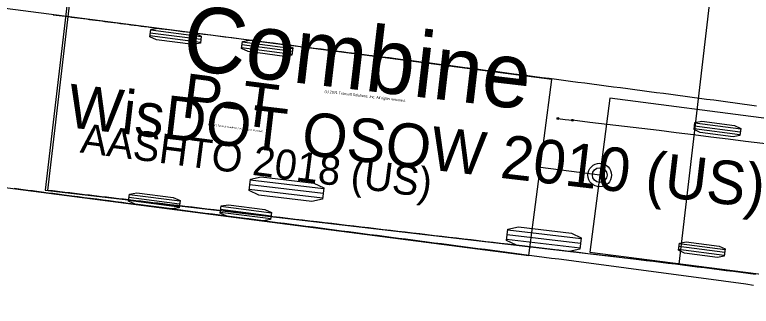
# Model space of a CAD drawing. Extents: x -14 to 1565148, y -25 to 642856.
# Drawn here: x 1564698.39 to 1564731.62, y 636284.95 to 636298.09 of the extents above; entities that cross this region are included whole.
import ezdxf

# ---------------------------------------------------------------- set-up
doc = ezdxf.new("R2010")
doc.units = 0
doc.layers.add('PV_P_Curb', color=7, linetype='Continuous')

msp = doc.modelspace()

# ---------------------------------------------------------------- linework, layer by layer
at = {"layer": 'PV_P_Curb'}
for p, q in [((1564701.133, 636301.885), (1564699.765, 636290.185)), ((1564722.618, 636295.178), (1564695.843, 636298.65)), ((1564728.37, 636286.841), (1564729.738, 636298.541)), ((1564706.801, 636297.098), (1564704.52, 636297.394)), ((1564706.767, 636296.84), (1564704.486, 636297.136)), ((1564706.784, 636296.969), (1564704.503, 636297.265)), ((1564710.916, 636296.433), (1564708.635, 636296.729)), ((1564710.933, 636296.562), (1564708.652, 636296.858)), ((1564710.899, 636296.304), (1564708.618, 636296.6)), ((1564721.59, 636287.245), (1564722.618, 636295.178)), ((1564722.618, 636295.178), (1564722.618, 636295.178)), ((1564725.232, 636294.335), (1564724.332, 636287.393)), ((1564744.074, 636291.892), (1564725.232, 636294.335)), ((1564731.125, 636292.804), (1564729.059, 636293.072)), ((1564731.142, 636292.933), (1564729.076, 636293.201)), ((1564731.109, 636292.675), (1564729.043, 636292.943)), ((1564724.782, 636290.864), (1564722.104, 636291.211)), ((1564694.814, 636290.717), (1564721.59, 636287.245)), ((1564724.782, 636290.864), (1564724.782, 636290.864)), ((1564712.299, 636290.035), (1564708.988, 636290.422)), ((1564712.323, 636290.242), (1564709.013, 636290.629)), ((1564699.765, 636290.185), (1564728.37, 636286.841)), ((1564712.275, 636289.828), (1564708.964, 636290.215)), ((1564705.805, 636289.423), (1564703.524, 636289.718)), ((1564705.822, 636289.552), (1564703.541, 636289.848)), ((1564705.839, 636289.681), (1564703.558, 636289.977)), ((1564709.971, 636289.145), (1564707.69, 636289.441)), ((1564709.937, 636288.887), (1564707.657, 636289.183)), ((1564709.954, 636289.016), (1564707.673, 636289.312)), ((1564723.916, 636287.781), (1564720.605, 636288.168)), ((1564723.94, 636287.988), (1564720.629, 636288.375)), ((1564723.892, 636287.574), (1564720.581, 636287.961)), ((1564730.438, 636287.5), (1564728.372, 636287.768)), ((1564724.332, 636287.393), (1564743.174, 636284.95)), ((1564730.404, 636287.241), (1564728.338, 636287.509)), ((1564730.421, 636287.371), (1564728.355, 636287.638))]:
    msp.add_line(p, q, dxfattribs=at)
for points in [[(1564731.805, 636286.385), (1564731.477, 636286.427), (1564731.149, 636286.469), (1564730.821, 636286.511), (1564730.492, 636286.553), (1564730.164, 636286.594), (1564729.836, 636286.636), (1564729.508, 636286.677), (1564729.179, 636286.718), (1564728.851, 636286.759), (1564728.523, 636286.8), (1564728.194, 636286.841), (1564727.866, 636286.882), (1564727.537, 636286.922), (1564727.209, 636286.963), (1564726.88, 636287.003), (1564726.552, 636287.043), (1564726.223, 636287.083), (1564725.895, 636287.123), (1564725.566, 636287.163), (1564725.238, 636287.202), (1564724.909, 636287.242), (1564724.581, 636287.281), (1564724.252, 636287.32), (1564723.923, 636287.359), (1564723.594, 636287.398), (1564723.265, 636287.437), (1564722.936, 636287.476), (1564722.607, 636287.514), (1564722.278, 636287.553), (1564721.948, 636287.591), (1564721.619, 636287.63), (1564721.289, 636287.668), (1564720.96, 636287.707), (1564720.63, 636287.745), (1564720.3, 636287.784), (1564719.97, 636287.823), (1564719.64, 636287.861), (1564719.31, 636287.9), (1564718.98, 636287.938), (1564718.65, 636287.977), (1564718.319, 636288.016), (1564717.989, 636288.054), (1564717.658, 636288.093), (1564717.327, 636288.132), (1564716.997, 636288.17), (1564716.666, 636288.209), (1564716.335, 636288.248), (1564716.004, 636288.286), (1564715.673, 636288.325), (1564715.342, 636288.364), (1564715.011, 636288.402), (1564714.679, 636288.441), (1564714.348, 636288.48), (1564714.017, 636288.519), (1564713.685, 636288.557), (1564713.354, 636288.596), (1564713.022, 636288.635), (1564712.691, 636288.674), (1564712.359, 636288.712), (1564712.028, 636288.751), (1564711.696, 636288.79), (1564711.364, 636288.829), (1564711.032, 636288.867), (1564710.701, 636288.906), (1564710.369, 636288.945), (1564710.037, 636288.984), (1564709.705, 636289.023), (1564709.373, 636289.061), (1564709.042, 636289.1), (1564708.71, 636289.139), (1564708.378, 636289.178), (1564708.047, 636289.216), (1564707.715, 636289.255), (1564707.383, 636289.294), (1564707.052, 636289.333), (1564706.72, 636289.372), (1564706.389, 636289.41), (1564706.058, 636289.449), (1564705.726, 636289.488), (1564705.395, 636289.526), (1564705.284, 636289.539), (1564705.174, 636289.552), (1564705.063, 636289.565), (1564704.953, 636289.578), (1564704.842, 636289.591), (1564704.732, 636289.604), (1564704.621, 636289.617), (1564704.511, 636289.63), (1564704.4, 636289.643), (1564704.29, 636289.656), (1564704.18, 636289.669), (1564704.069, 636289.681), (1564703.959, 636289.694), (1564703.848, 636289.707), (1564703.738, 636289.72), (1564703.628, 636289.733), (1564703.517, 636289.746), (1564703.407, 636289.759), (1564703.297, 636289.772), (1564703.186, 636289.785), (1564703.076, 636289.798), (1564702.966, 636289.81), (1564702.855, 636289.823), (1564702.745, 636289.836), (1564702.635, 636289.849), (1564702.524, 636289.862), (1564702.414, 636289.875), (1564702.303, 636289.888), (1564702.193, 636289.901), (1564702.083, 636289.914), (1564701.972, 636289.927), (1564701.862, 636289.939), (1564701.752, 636289.952), (1564701.641, 636289.965), (1564701.531, 636289.978), (1564701.421, 636289.991), (1564701.31, 636290.004), (1564701.2, 636290.017), (1564701.089, 636290.03), (1564700.979, 636290.043), (1564700.869, 636290.056), (1564700.758, 636290.069), (1564700.648, 636290.081), (1564700.538, 636290.094), (1564700.427, 636290.107), (1564700.317, 636290.12), (1564700.207, 636290.133), (1564700.096, 636290.146), (1564699.986, 636290.159), (1564699.876, 636290.172), (1564701.243, 636301.873)], [(1564700.123, 636298.095), (1564700.259, 636298.078), (1564700.396, 636298.06), (1564700.532, 636298.042), (1564700.668, 636298.024), (1564700.805, 636298.007), (1564700.941, 636297.989), (1564701.078, 636297.971), (1564701.215, 636297.954), (1564701.351, 636297.936), (1564701.488, 636297.918), (1564701.625, 636297.9), (1564701.762, 636297.883), (1564701.9, 636297.865), (1564702.037, 636297.847), (1564702.174, 636297.829), (1564702.312, 636297.811), (1564702.449, 636297.794), (1564702.587, 636297.776), (1564702.724, 636297.758), (1564702.862, 636297.74), (1564703, 636297.722), (1564703.153, 636297.702), (1564703.31, 636297.682), (1564703.467, 636297.662), (1564703.624, 636297.641), (1564703.78, 636297.621), (1564703.935, 636297.601), (1564704.091, 636297.581), (1564704.245, 636297.561), (1564704.4, 636297.542), (1564704.554, 636297.522), (1564704.708, 636297.502), (1564705.014, 636297.463), (1564705.335, 636297.422), (1564705.654, 636297.381), (1564705.973, 636297.341), (1564706.291, 636297.3), (1564706.609, 636297.26), (1564706.925, 636297.22), (1564707.241, 636297.179), (1564707.556, 636297.139), (1564707.87, 636297.099), (1564708.184, 636297.06), (1564708.496, 636297.02), (1564708.808, 636296.98), (1564709.12, 636296.941), (1564709.431, 636296.901), (1564709.741, 636296.862), (1564710.051, 636296.822), (1564710.36, 636296.783), (1564710.669, 636296.744), (1564710.977, 636296.704), (1564711.286, 636296.665), (1564711.593, 636296.626), (1564711.901, 636296.587), (1564712.208, 636296.548), (1564712.515, 636296.509), (1564712.822, 636296.47), (1564713.129, 636296.431), (1564713.436, 636296.392), (1564713.743, 636296.352), (1564714.049, 636296.313), (1564714.356, 636296.274), (1564714.663, 636296.235), (1564714.97, 636296.196), (1564715.278, 636296.157), (1564715.586, 636296.117), (1564715.894, 636296.078), (1564716.202, 636296.038), (1564716.511, 636295.999), (1564716.821, 636295.959), (1564717.131, 636295.919), (1564717.441, 636295.88), (1564717.753, 636295.84), (1564718.065, 636295.8), (1564718.377, 636295.759), (1564718.691, 636295.719), (1564719.005, 636295.679), (1564719.319, 636295.638), (1564719.635, 636295.597), (1564719.951, 636295.557), (1564720.268, 636295.516), (1564720.585, 636295.475), (1564720.904, 636295.434), (1564721.222, 636295.392), (1564721.542, 636295.351), (1564721.861, 636295.309), (1564722.182, 636295.268), (1564722.502, 636295.226), (1564722.824, 636295.184), (1564723.145, 636295.143), (1564723.467, 636295.101), (1564723.789, 636295.059), (1564724.111, 636295.017), (1564724.433, 636294.974), (1564724.756, 636294.932), (1564725.079, 636294.89), (1564725.402, 636294.847), (1564725.725, 636294.805), (1564726.047, 636294.763), (1564726.37, 636294.72), (1564726.694, 636294.677), (1564727.017, 636294.635), (1564727.34, 636294.592), (1564727.663, 636294.549), (1564727.986, 636294.507), (1564728.309, 636294.464), (1564728.632, 636294.421), (1564728.955, 636294.378), (1564729.278, 636294.335), (1564729.601, 636294.292), (1564729.924, 636294.249), (1564730.247, 636294.206), (1564730.57, 636294.162), (1564730.893, 636294.119), (1564731.216, 636294.076), (1564731.539, 636294.032), (1564731.863, 636293.989)], [(1564722.896, 636293.411), (1564723.227, 636293.372), (1564723.558, 636293.333)], [(1564731.718, 636285.893), (1564731.38, 636285.939), (1564731.043, 636285.985), (1564730.705, 636286.03), (1564730.367, 636286.076), (1564730.029, 636286.122), (1564729.691, 636286.167), (1564729.354, 636286.213), (1564729.016, 636286.258), (1564728.678, 636286.303), (1564728.34, 636286.349), (1564728.002, 636286.394), (1564727.664, 636286.439), (1564727.327, 636286.484), (1564726.989, 636286.529), (1564726.651, 636286.574), (1564726.313, 636286.619), (1564725.976, 636286.664), (1564725.638, 636286.709), (1564725.301, 636286.754), (1564724.963, 636286.799), (1564724.626, 636286.843), (1564724.289, 636286.888), (1564723.952, 636286.932), (1564723.615, 636286.977), (1564723.279, 636287.021), (1564722.943, 636287.066), (1564722.607, 636287.11), (1564722.271, 636287.154), (1564721.937, 636287.198), (1564721.602, 636287.242), (1564721.268, 636287.285), (1564720.935, 636287.329), (1564720.603, 636287.373), (1564720.271, 636287.416), (1564719.939, 636287.459), (1564719.609, 636287.502), (1564719.279, 636287.544), (1564718.95, 636287.587), (1564718.622, 636287.63), (1564718.294, 636287.672), (1564717.967, 636287.714), (1564717.641, 636287.757), (1564717.316, 636287.799), (1564716.991, 636287.841), (1564716.667, 636287.883), (1564716.343, 636287.925), (1564716.02, 636287.967), (1564715.698, 636288.009), (1564715.375, 636288.05), (1564715.054, 636288.092), (1564714.732, 636288.134), (1564714.411, 636288.175), (1564714.09, 636288.217), (1564713.77, 636288.259), (1564713.449, 636288.3), (1564713.128, 636288.342), (1564712.808, 636288.383), (1564712.487, 636288.425), (1564712.166, 636288.467), (1564711.845, 636288.508), (1564711.524, 636288.55), (1564711.202, 636288.592), (1564710.881, 636288.633), (1564710.559, 636288.675), (1564710.236, 636288.717), (1564709.913, 636288.759), (1564709.59, 636288.801), (1564709.266, 636288.843), (1564708.942, 636288.885), (1564708.617, 636288.927), (1564708.291, 636288.969), (1564707.965, 636289.011), (1564707.638, 636289.053), (1564707.311, 636289.096), (1564706.982, 636289.138), (1564706.653, 636289.181), (1564706.323, 636289.223), (1564705.992, 636289.266), (1564705.661, 636289.309), (1564705.328, 636289.352), (1564704.995, 636289.395), (1564704.661, 636289.438), (1564704.326, 636289.482), (1564703.77, 636289.553), (1564703.491, 636289.589), (1564703.211, 636289.626), (1564702.931, 636289.662), (1564702.651, 636289.698), (1564702.37, 636289.734), (1564702.089, 636289.771), (1564701.807, 636289.807), (1564701.525, 636289.844), (1564701.242, 636289.88), (1564700.959, 636289.917), (1564700.717, 636289.948), (1564700.615, 636289.961), (1564700.513, 636289.974), (1564700.41, 636289.988), (1564700.308, 636290.001), (1564700.206, 636290.014), (1564700.103, 636290.027), (1564700.001, 636290.04), (1564699.899, 636290.054), (1564699.796, 636290.067), (1564699.694, 636290.08), (1564699.591, 636290.093), (1564699.488, 636290.107), (1564699.386, 636290.12), (1564699.283, 636290.133), (1564699.181, 636290.146), (1564699.078, 636290.16), (1564698.975, 636290.173), (1564698.873, 636290.186), (1564698.77, 636290.2), (1564698.667, 636290.213), (1564698.564, 636290.226), (1564698.462, 636290.24), (1564698.359, 636290.253)]]:
    msp.add_lwpolyline(points, dxfattribs=at)
for points in [[(1564706.805, 636297.13), (1564706.763, 636296.808), (1564706.431, 636296.752), (1564704.789, 636296.965), (1564704.482, 636297.103), (1564704.524, 636297.426), (1564704.856, 636297.481), (1564706.498, 636297.269)], [(1564710.937, 636296.594), (1564710.895, 636296.272), (1564710.563, 636296.216), (1564708.921, 636296.429), (1564708.614, 636296.568), (1564708.656, 636296.89), (1564708.988, 636296.946), (1564710.63, 636296.733)], [(1564731.146, 636292.965), (1564731.105, 636292.643), (1564730.803, 636292.583), (1564729.315, 636292.776), (1564729.038, 636292.911), (1564729.08, 636293.233), (1564729.382, 636293.293), (1564730.87, 636293.1)], [(1564712.329, 636290.293), (1564712.269, 636289.777), (1564711.787, 636289.675), (1564709.404, 636289.954), (1564708.958, 636290.164), (1564709.019, 636290.68), (1564709.5, 636290.782), (1564711.884, 636290.503)], [(1564705.843, 636289.713), (1564705.801, 636289.391), (1564705.469, 636289.335), (1564703.827, 636289.548), (1564703.52, 636289.686), (1564703.562, 636290.009), (1564703.894, 636290.064), (1564705.536, 636289.851)], [(1564709.975, 636289.177), (1564709.933, 636288.855), (1564709.601, 636288.799), (1564707.959, 636289.012), (1564707.652, 636289.151), (1564707.694, 636289.473), (1564708.026, 636289.529), (1564709.668, 636289.316)], [(1564723.946, 636288.039), (1564723.886, 636287.523), (1564723.404, 636287.421), (1564721.02, 636287.7), (1564720.575, 636287.91), (1564720.635, 636288.426), (1564721.117, 636288.527), (1564723.501, 636288.249)], [(1564730.442, 636287.532), (1564730.4, 636287.209), (1564730.098, 636287.15), (1564728.611, 636287.343), (1564728.334, 636287.477), (1564728.376, 636287.8), (1564728.678, 636287.859), (1564730.165, 636287.666)]]:
    msp.add_lwpolyline(points, close=True, dxfattribs=at)
for centre, radius in [((1564722.896, 636293.411), 0.0417), ((1564723.558, 636293.333), 0.0417), ((1564723.558, 636293.333), 0.0417), ((1564724.782, 636290.864), 0.533), ((1564724.782, 636290.864), 0.333)]:
    msp.add_circle(centre, radius, dxfattribs=at)
msp.add_arc((1564628.539, 635483.309), 815.578, 79.777812, 83.309548, dxfattribs=at)

# ---------------------------------------------------------------- texts
for s, height, rotation, p in [('Combine', 2.945, 353.3322, (1564705.865, 636295.639)), ('P-T', 2, 352.6118, (1564705.856, 636293.48)), ('WisDOT OSOW 2010 (US)', 1.96333, 353.3322, (1564700.689, 636293.032)), ('(c) 2021 Transoft Solutions, Inc. All rights reserved.', 0.1178, 353.3322, (1564712.36, 636294.583)), ('AASHTO 2018 (US)', 1.33333, 352.6118, (1564701.304, 636291.885)), ('(c) 2021 Transoft Solutions, Inc. All rights reserved.', 0.08, 352.6118, (1564707.094, 636293.117))]:
    msp.add_text(s, height=height, rotation=rotation, dxfattribs=at).set_placement(p)

doc.saveas('drawing.dxf')
